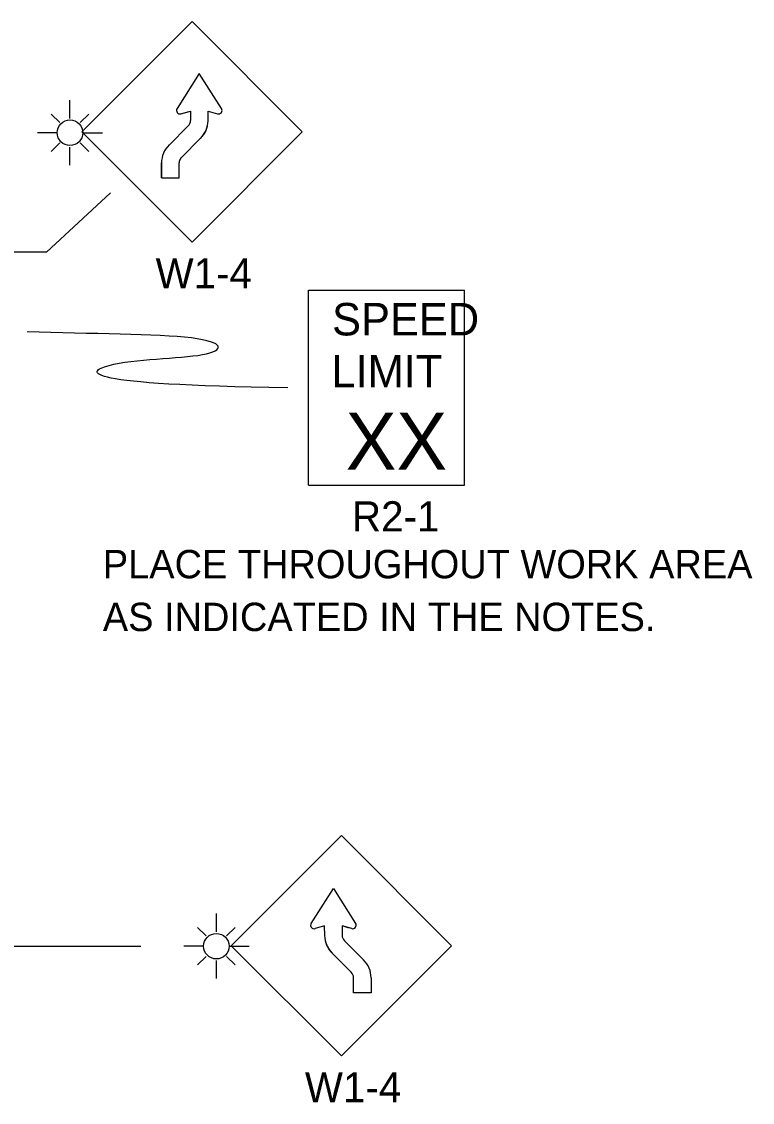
# Model space of a CAD drawing. Extents: x 16525 to 18478, y 5730 to 6927.
# Drawn here: x 17246.6 to 17426.8, y 6401.9 to 6668.2 of the extents above; entities that cross this region are included whole.
import ezdxf

# ---------------------------------------------------------------- set-up
doc = ezdxf.new("R2010")
doc.units = 0
doc.layers.add('TRAFFIC_SIGNS_PR', color=7, linetype='Continuous')
doc.layers.add('TYPICAL_TEXT_DIMEN_PR', color=7, linetype='Continuous')

msp = doc.modelspace()

# ---------------------------------------------------------------- linework, layer by layer
at = {"layer": 'TRAFFIC_SIGNS_PR'}
for p, q in [((17288.66, 6668.23), (17261.51, 6641.08)), ((17315.81, 6641.08), (17288.66, 6668.23)), ((17258.56, 6644.4), (17258.56, 6648.91)), ((17256.05, 6643.36), (17253.94, 6645.47)), ((17261.07, 6643.36), (17263.18, 6645.47)), ((17283, 6637.83), (17287.72, 6642.54)), ((17287.72, 6642.54), (17283, 6637.83)), ((17255.41, 6640.85), (17250.57, 6640.85)), ((17261.51, 6641.08), (17288.66, 6613.93)), ((17261.71, 6640.85), (17266.6, 6640.85)), ((17286.05, 6634.78), (17290.77, 6639.49)), ((17286.06, 6634.78), (17290.77, 6639.49)), ((17288.66, 6613.93), (17315.81, 6641.08)), ((17256.05, 6638.34), (17253.94, 6636.23)), ((17258.56, 6632.88), (17258.56, 6637.29)), ((17261.07, 6638.34), (17263.18, 6636.23)), ((17281.14, 6629.71), (17281.14, 6633.41)), ((17285.45, 6629.71), (17285.45, 6633.41)), ((17281.14, 6629.71), (17285.45, 6629.71)), ((17317.41, 6602.05), (17355.81, 6602.05)), ((17317.41, 6554.05), (17317.41, 6602.05)), ((17355.81, 6554.05), (17355.81, 6602.05)), ((17317.41, 6554.05), (17355.81, 6554.05)), ((17298.32, 6440.53), (17325.47, 6467.68)), ((17352.63, 6440.53), (17325.47, 6467.68)), ((17294.66, 6443.98), (17294.66, 6448.48)), ((17292.15, 6442.94), (17290.04, 6445.05)), ((17297.18, 6442.94), (17299.29, 6445.05)), ((17330.95, 6437.06), (17326.23, 6441.78)), ((17326.23, 6441.78), (17330.95, 6437.06)), ((17291.51, 6440.42), (17286.67, 6440.42)), ((17297.82, 6440.42), (17302.7, 6440.42)), ((17325.47, 6413.38), (17298.32, 6440.53)), ((17352.63, 6440.53), (17325.47, 6413.38)), ((17292.15, 6437.91), (17290.04, 6435.8)), ((17294.66, 6432.46), (17294.66, 6436.87)), ((17297.18, 6437.91), (17299.28, 6435.8)), ((17327.89, 6434.01), (17323.18, 6438.73)), ((17327.89, 6434.01), (17323.18, 6438.73))]:
    msp.add_line(p, q, dxfattribs=at)
for points in [[(17295.92, 6646.82), (17290.44, 6655.43), (17284.96, 6646.82)], [(17295.92, 6646.82), (17290.44, 6655.43), (17284.96, 6646.82)], [(17285.92, 6645.52), (17288.28, 6646.17), (17288.28, 6643.87)], [(17285.92, 6645.52), (17286.75, 6645.75), (17288.28, 6646.17), (17288.28, 6643.87)], [(17292.59, 6643.8), (17292.6, 6646.17), (17294.96, 6645.52)], [(17281.13, 6633.41), (17281.14, 6629.71), (17285.45, 6629.71), (17285.45, 6633.41)], [(17318.02, 6446.05), (17323.51, 6454.66), (17328.99, 6446.05)], [(17318.03, 6446.05), (17323.51, 6454.66), (17328.99, 6446.05)], [(17321.36, 6443.04), (17321.35, 6445.4), (17318.99, 6444.75)], [(17321.36, 6443.04), (17321.35, 6445.4), (17318.99, 6444.75)], [(17328.03, 6444.75), (17325.67, 6445.4), (17325.67, 6443.11)], [(17328.03, 6444.75), (17327.19, 6444.98), (17325.67, 6445.4), (17325.67, 6443.11)], [(17332.81, 6432.64), (17332.81, 6428.94), (17328.5, 6428.94), (17328.5, 6432.64)]]:
    msp.add_lwpolyline(points, dxfattribs=at)
for centre in [(17258.56, 6640.85), (17294.66, 6440.42)]:
    msp.add_circle(centre, 3.15, dxfattribs=at)
for centre, radius, start, end in [((17285.69, 6646.35), 0.864, 147.5204, 285.3986), ((17285.69, 6646.35), 0.866, 147.5288, 285.3852), ((17295.19, 6646.36), 0.866, 254.6799, 32.2804), ((17286.43, 6643.87), 1.85, 314.2125, 0), ((17286.43, 6643.87), 1.85, 314.2123, 0.1238), ((17286.43, 6643.87), 6.17, 314.2125, 359.3819), ((17286.43, 6643.87), 6.17, 314.7687, 359.3755), ((17287.3, 6633.41), 6.17, 134.2125, 180), ((17287.3, 6633.41), 6.17, 134.2125, 180), ((17287.3, 6633.41), 6.17, 134.2117, 180), ((17287.3, 6633.41), 1.85, 132.372, 180), ((17287.3, 6633.41), 1.85, 134.2125, 180), ((17318.76, 6445.59), 0.866, 147.7292, 285.3172), ((17318.76, 6445.59), 0.866, 147.7196, 285.3201), ((17308.91, 6451.85), 10.8, 327.5335, 327.5431), ((17321.84, 6434.33), 10.8, 105.3192, 105.32), ((17328.26, 6445.59), 0.866, 254.6148, 32.4712), ((17327.52, 6443.1), 6.17, 180.6181, 225.7875), ((17327.52, 6443.1), 6.17, 180.6245, 225.2313), ((17327.52, 6443.1), 1.85, 179.8762, 225.7877), ((17327.52, 6443.1), 1.85, 180, 225.7875), ((17326.64, 6432.64), 6.17, 0, 45.7883), ((17326.64, 6432.64), 1.85, 0, 47.628)]:
    msp.add_arc(centre, radius, start, end, dxfattribs=at)
at = {"layer": 'TYPICAL_TEXT_DIMEN_PR'}
for p, q in [((17252.79, 6611.4), (17268.52, 6626.05)), ((17252.79, 6611.4), (17226.95, 6611.4)), ((17276.02, 6440.36), (17228.05, 6440.36))]:
    msp.add_line(p, q, dxfattribs=at)
msp.add_open_spline([(17312.25, 6578.04), (17261.06, 6578.66), (17263.06, 6585.16), (17296.82, 6585.16), (17296.82, 6591.31), (17263.48, 6591.31), (17248.02, 6591.76)], degree=3, dxfattribs=at)

# ---------------------------------------------------------------- texts
at = {"layer": 'TRAFFIC_SIGNS_PR'}
for s, height, p in [('W1-4', 7.44, (17279.66, 6602.49)), ('SPEED', 8, (17323.18, 6590.91)), ('LIMIT', 8, (17323.02, 6578.11)), ('XX', 14.031, (17326.53, 6557.81)), ('R2-1', 7.44, (17328.09, 6542.61)), ('PLACE THROUGHOUT WORK AREA', 7, (17266.66, 6531.06)), ('AS INDICATED IN THE NOTES.', 7, (17266.66, 6518.06)), ('W1-4', 7.44, (17316.48, 6401.94))]:
    msp.add_text(s, height=height, dxfattribs=at).set_placement(p)

doc.saveas('drawing.dxf')
